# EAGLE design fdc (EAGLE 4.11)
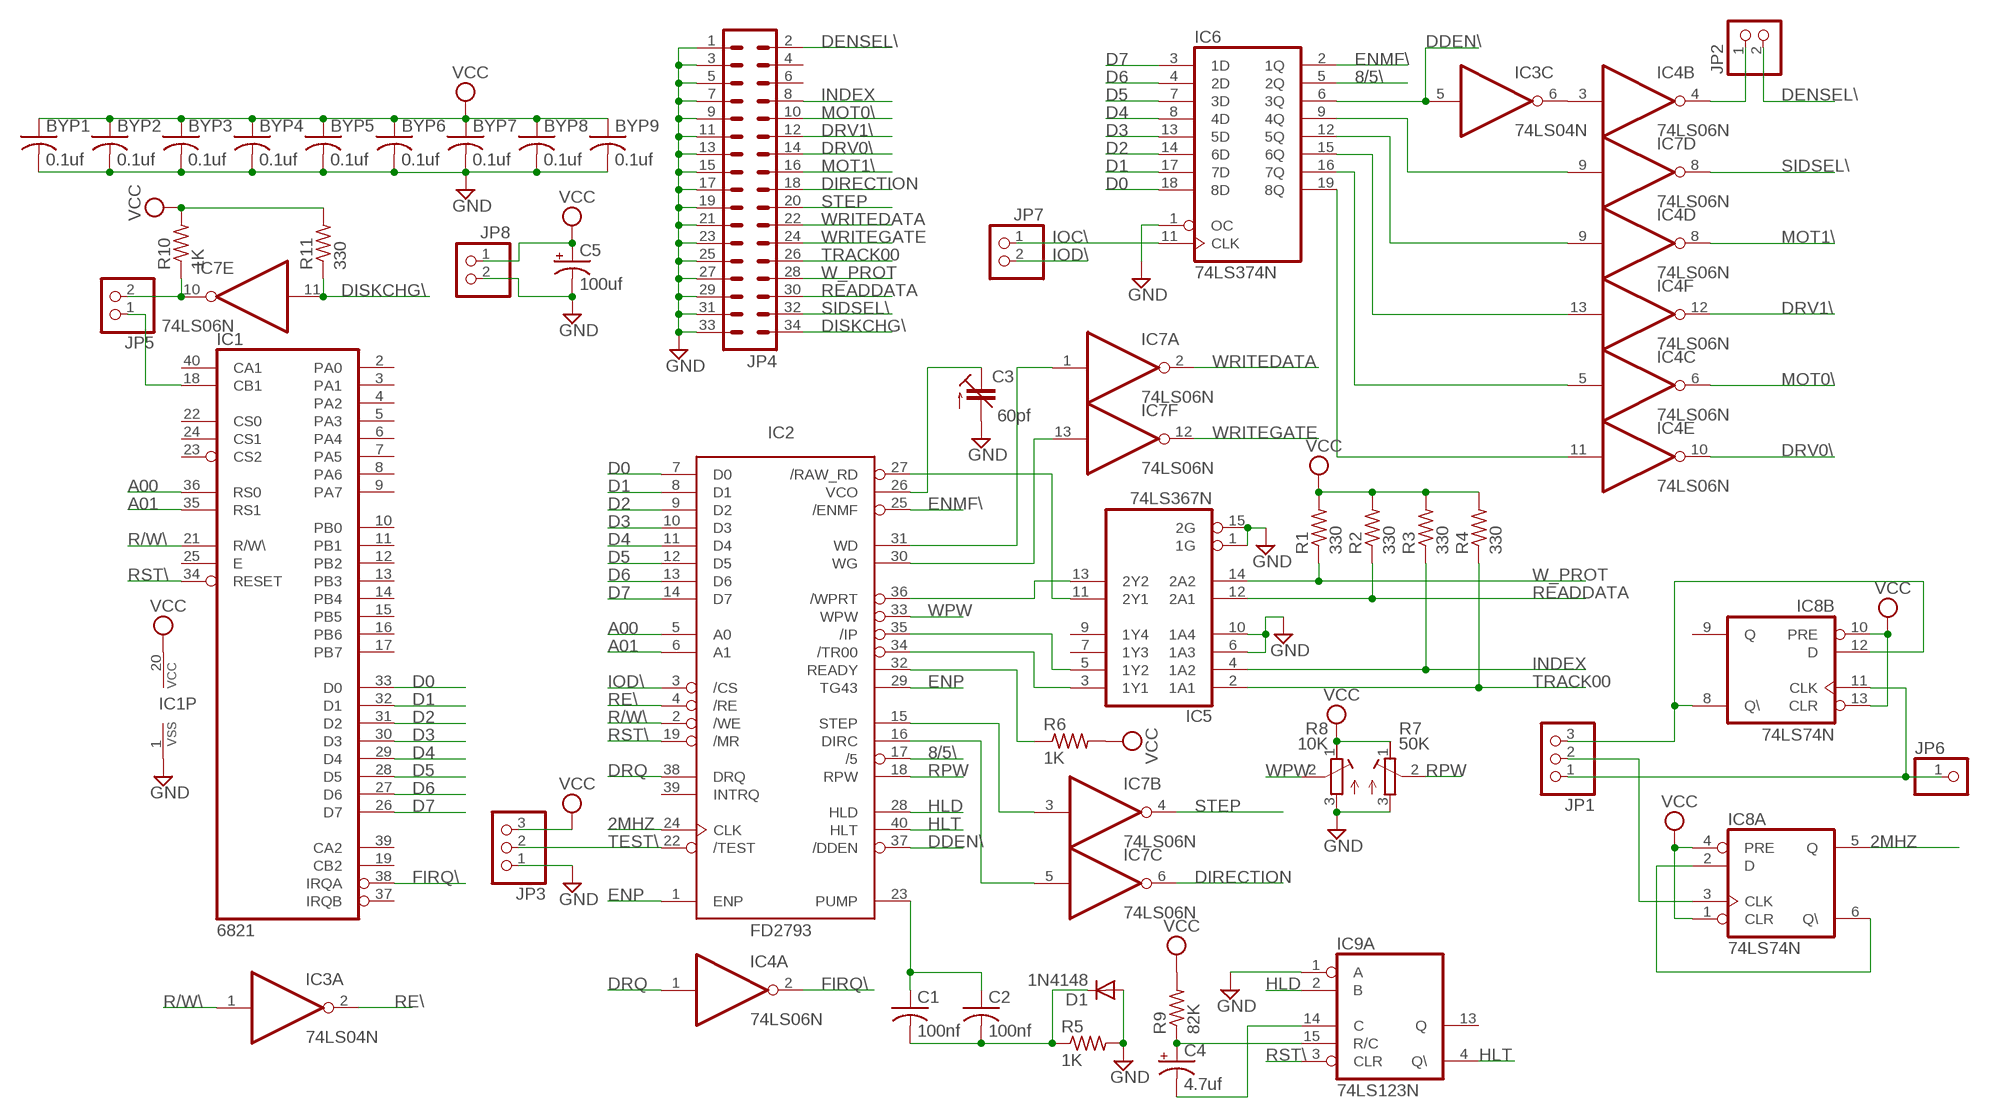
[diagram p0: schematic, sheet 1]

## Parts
BYP1  0.1uf  C-US050-025X075  [C050-025X075]
BYP2  0.1uf  C-US050-025X075  [C050-025X075]
BYP3  0.1uf  C-US050-025X075  [C050-025X075]
BYP4  0.1uf  C-US050-025X075  [C050-025X075]
BYP5  0.1uf  C-US050-025X075  [C050-025X075]
BYP6  0.1uf  C-US050-025X075  [C050-025X075]
BYP7  0.1uf  C-US050-025X075  [C050-025X075]
BYP8  0.1uf  C-US050-025X075  [C050-025X075]
BYP9  0.1uf  C-US050-025X075  [C050-025X075]
C1  100nf  C-US050-025X075  [C050-025X075]
C2  100nf  C-US050-025X075  [C050-025X075]
C3  60pf  C-TRIMM808  [CTRIM808-BC]
C4  4.7uf  CPOL-USE15-5AXIAL  [E15-5]
C5  100uf  CPOL-USE15-5AXIAL  [E15-5]
D1  1N4148  [DO35-10]
IC1  6821  [DIL40]
IC2  FD2793  [DIL40]
IC3  74LS04N  [DIL14]
IC4  74LS06N  [DIL14]
IC5  74LS367N  [DIL16]
IC6  74LS374N  [DIL20]
IC7  74LS06N  [DIL14]
IC8  74LS74N  [DIL14]
IC9  74LS123N  [DIL16]
JP1  PINHD-1X3  [1X03]
JP2  PINHD-1X2  [1X02]
JP3  PINHD-1X3  [1X03]
JP4  MA17-2  [MA17-2]
JP5  PINHD-1X2  [1X02]
JP6  PINHD-1X1  [1X01]
JP7  PINHD-1X2  [1X02]
JP8  PINHD-1X2  [1X02]
R1  330  R-US_0207/10  [0207/10]
R2  330  R-US_0207/10  [0207/10]
R3  330  R-US_0207/10  [0207/10]
R4  330  R-US_0207/10  [0207/10]
R5  1K  R-US_0207/10  [0207/10]
R6  1K  R-US_0207/10  [0207/10]
R7  50K  R-TRIMM43P  [RTRIM43P]
R8  10K  R-TRIMM43P  [RTRIM43P]
R9  82K  R-US_0207/10  [0207/10]
R10  1K  R-US_0207/10  [0207/10]
R11  330  R-US_0207/10  [0207/10]

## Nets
2MHZ: IC2.24(CLK) IC8.5(A:Q)
8/5\: IC2.17(/5) IC6.5(2Q)
A00: IC1.36(RS0) IC2.5(A0)
A01: IC1.35(RS1) IC2.6(A1)
CB1: IC1.18(CB1) JP5.1
D0: IC1.33(D0) IC2.7(D0) IC6.18(8D)
D1: IC1.32(D1) IC2.8(D1) IC6.17(7D)
D2: IC1.31(D2) IC2.9(D2) IC6.14(6D)
D3: IC1.30(D3) IC2.10(D3) IC6.13(5D)
D4: IC1.29(D4) IC2.11(D4) IC6.8(4D)
D5: IC1.28(D5) IC2.12(D5) IC6.7(3D)
D6: IC1.27(D6) IC2.13(D6) IC6.4(2D)
D7: IC1.26(D7) IC2.14(D7) IC6.3(1D)
DDEN\: IC2.37(/DDEN) IC3.5(C:I) IC6.6(3Q)
DENSEL\: JP2.2 JP4.2
DIRECTION: IC7.6(C:O) JP4.18
DISKCHG\: IC7.11(E:I) JP4.34 R11.1
DRQ: IC2.38(DRQ) IC4.1(A:I)
DRV0\: IC4.10(E:O) JP4.14
DRV1\: IC4.12(F:O) JP4.12
ENMF\: IC2.25(/ENMF) IC6.2(1Q)
ENP: IC2.1(ENP) IC2.29(TG43)
FIRQ\: IC1.38(IRQA) IC4.2(A:O)
GND: BYP1.2 BYP2.2 BYP3.2 BYP4.2 BYP5.2 BYP6.2 BYP7.2 BYP8.2 BYP9.2 C3.2(A) C5.- D1.A IC1.1(VSS) IC5.1(1G) IC5.6(1A3) IC5.10(1A4) IC5.15(2G) IC6.1(OC) IC9.1(A:A) JP3.1 JP4.1 JP4.3 JP4.5 JP4.7 JP4.9 JP4.11 JP4.13 JP4.15 JP4.17 JP4.19 JP4.21 JP4.23 JP4.25 JP4.27 JP4.29 JP4.31 JP4.33 JP8.2 R5.2 R7.3(E) R8.3(E)
HLD: IC2.28(HLD) IC9.2(A:B)
HLT: IC2.40(HLT) IC9.4(A:Q\)
INDEX: IC5.4(1A2) JP4.8 R3.1
IOC\: IC6.11(CLK) JP7.1
IOD\: IC2.3(/CS) JP7.2
MOT0\: IC4.6(C:O) JP4.10
MOT1\: IC4.8(D:O) JP4.16
N$1: IC3.6(C:O) IC4.3(B:I)
N$2: IC4.4(B:O) JP2.1
N$3: IC2.27(/RAW_RD) IC5.11(2Y1)
N$4: IC4.11(E:I) IC6.19(8Q)
N$5: IC4.5(C:I) IC6.16(7Q)
N$6: IC4.13(F:I) IC6.15(6Q)
N$7: IC4.9(D:I) IC6.12(5Q)
N$8: C4.+ IC9.15(A:R/C) R9.1
N$9: C4.- IC9.14(A:C)
N$10: IC2.32(READY) R6.1
N$11: IC6.9(4Q) IC7.9(D:I)
N$12: IC2.16(DIRC) IC7.5(C:I)
N$13: IC7.10(E:O) JP5.2 R10.1
N$14: IC2.34(/TR00) IC5.3(1Y1)
N$15: IC2.35(/IP) IC5.5(1Y2)
N$16: IC8.8(B:Q\) IC8.12(B:D) JP1.3
N$17: IC2.36(/WPRT) IC5.13(2Y2)
N$18: IC8.11(B:CLK) JP1.1 JP6.1
N$19: C3.1(E) IC2.26(VCO)
N$20: C1.2 C2.2 D1.C R5.1
N$21: IC2.31(WD) IC7.1(A:I)
N$22: IC2.30(WG) IC7.13(F:I)
N$24: IC2.15(STEP) IC7.3(B:I)
N$25: IC8.3(A:CLK) JP1.2
N$26: IC8.2(A:D) IC8.6(A:Q\)
PUMP: C1.1 C2.1 IC2.23(PUMP)
R/W\: IC1.21(R/W\) IC2.2(/WE) IC3.1(A:I)
RE\: IC2.4(/RE) IC3.2(A:O)
READDATA: IC5.12(2A1) JP4.30 R2.1
RPW: IC2.18(RPW) R7.2(S)
RST\: IC1.34(RESET) IC2.19(/MR) IC9.3(A:CLR)
SIDSEL\: IC7.8(D:O) JP4.32
STEP: IC7.4(B:O) JP4.20
TEST\: IC2.22(/TEST) JP3.2
TRACK00: IC5.2(1A1) JP4.26 R4.1
VCC [Power]: BYP1.1 BYP2.1 BYP3.1 BYP4.1 BYP5.1 BYP6.1 BYP7.1 BYP8.1 BYP9.1 C5.+ IC1.20(VCC) IC8.1(A:CLR) IC8.4(A:PRE) IC8.10(B:PRE) IC8.13(B:CLR) JP3.3 JP8.1 R1.2 R2.2 R3.2 R4.2 R6.2 R7.1(A) R8.1(A) R9.2 R10.2 R11.2
W_PROT: IC5.14(2A2) JP4.28 R1.1
WPW: IC2.33(WPW) R8.2(S)
WRITEDATA: IC7.2(A:O) JP4.22
WRITEGATE: IC7.12(F:O) JP4.24
Unconnected: IC1.2(PA0) IC1.3(PA1) IC1.4(PA2) IC1.5(PA3) IC1.6(PA4) IC1.7(PA5) IC1.8(PA6) IC1.9(PA7) IC1.10(PB0) IC1.11(PB1) IC1.12(PB2) IC1.13(PB3) IC1.14(PB4) IC1.15(PB5) IC1.16(PB6) IC1.17(PB7) IC1.19(CB2) IC1.22(CS0) IC1.23(CS2) IC1.24(CS1) IC1.25(E) IC1.37(IRQB) IC1.39(CA2) IC1.40(CA1) IC2.39(INTRQ) IC3.3(B:I) IC3.4(B:O) IC3.8(D:O) IC3.9(D:I) IC3.10(E:O) IC3.11(E:I) IC3.12(F:O) IC3.13(F:I) IC5.7(1Y3) IC5.9(1Y4) IC8.9(B:Q) IC9.5(B:Q) IC9.6(B:C) IC9.7(B:R/C) IC9.9(B:A) IC9.10(B:B) IC9.11(B:CLR) IC9.12(B:Q\) IC9.13(A:Q) JP4.4 JP4.6

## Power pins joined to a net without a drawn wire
GND: IC2.20(GND) IC3.7(P:GND) IC4.7(P:GND) IC5.8(GND) IC6.10(GND) IC7.7(P:GND) IC8.7(P:GND) IC9.8(P:GND)
VCC: IC2.21(VCC) IC3.14(P:VCC) IC4.14(P:VCC) IC5.16(VCC) IC6.20(VCC) IC7.14(P:VCC) IC8.14(P:VCC) IC9.16(P:VCC)

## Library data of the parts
BYP1-BYP9 C1 C2 = rcl:C-US: CAPACITOR, American symbol
C3 = rcl:C-TRIMM: Trimm capacitor
C4 C5 = rcl:CPOL-US: POLARIZED CAPACITOR, American symbol
D1 = diode:1N4148: DIODE
IC1 = micro-motorola:6821: MICROCONTROLLER/MEMORY DEVICE
IC2 = western-digital-devices:FD2793: FD2793 Floppy Disk Formatter/Controller
IC3 = 74xx-jameco:74*04: Hex INVERTER
IC4 IC7 = 74xx-jameco:74*06: Hex INVERTER, open collector high-voltage output
IC5 = 74xx-jameco:74*367: Hex BUS DRIVER, 3-state
IC6 = 74xx-jameco:74*374: Octal D type transparent LATCH, edge triggered
IC8 = 74xx-jameco:74*74: Dual D type positive edge triggered FLIP FLOP, preset and clear
IC9 = 74xx-jameco:74*123: Retriggerable monostable MULTIVIBRATOR
JP1 JP3 = pinhead:PINHD-1X3: PIN HEADER
JP2 JP5 JP7 JP8 = pinhead:PINHD-1X2: PIN HEADER
JP4 = con-lstb:MA17-2: PIN HEADER
JP6 = pinhead:PINHD-1X1: PIN HEADER
R1-R6 R9-R11 = rcl:R-US_: RESISTOR, American symbol
R7 R8 = rcl:R-TRIMM: Trimm resistor

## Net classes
1 Power: width 0.508 mm, drill 0.254 mm, clearance 0.254 mm

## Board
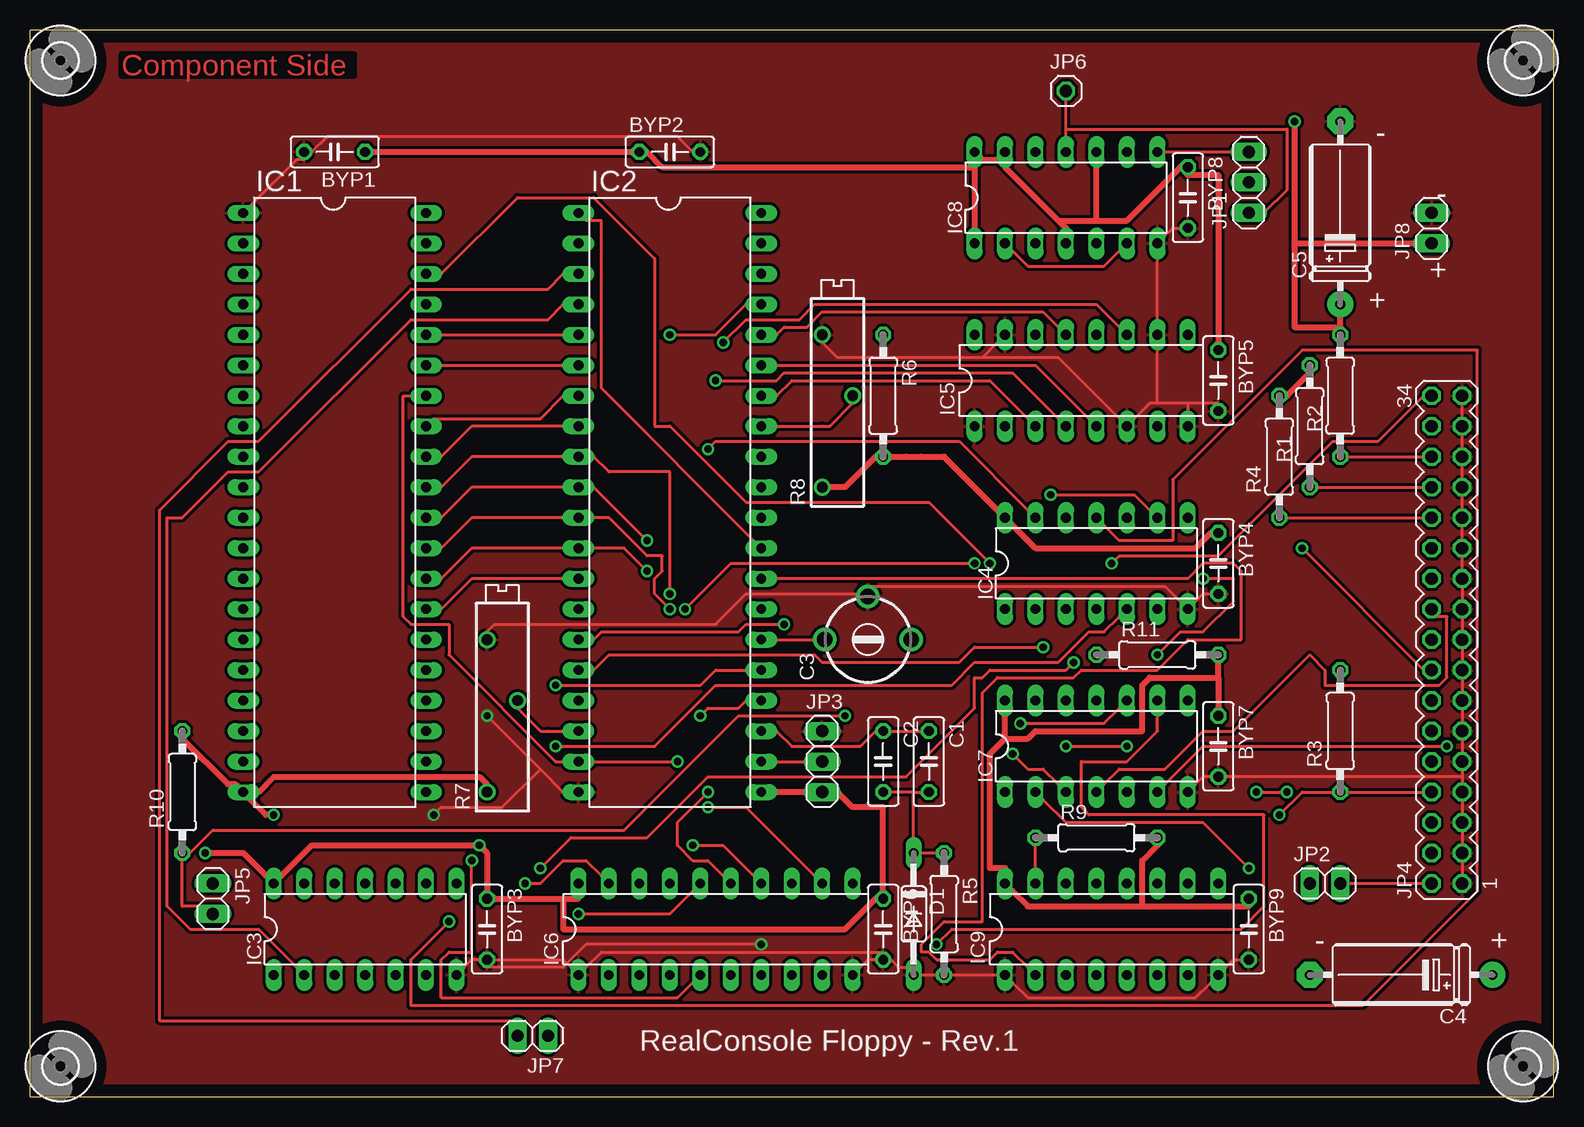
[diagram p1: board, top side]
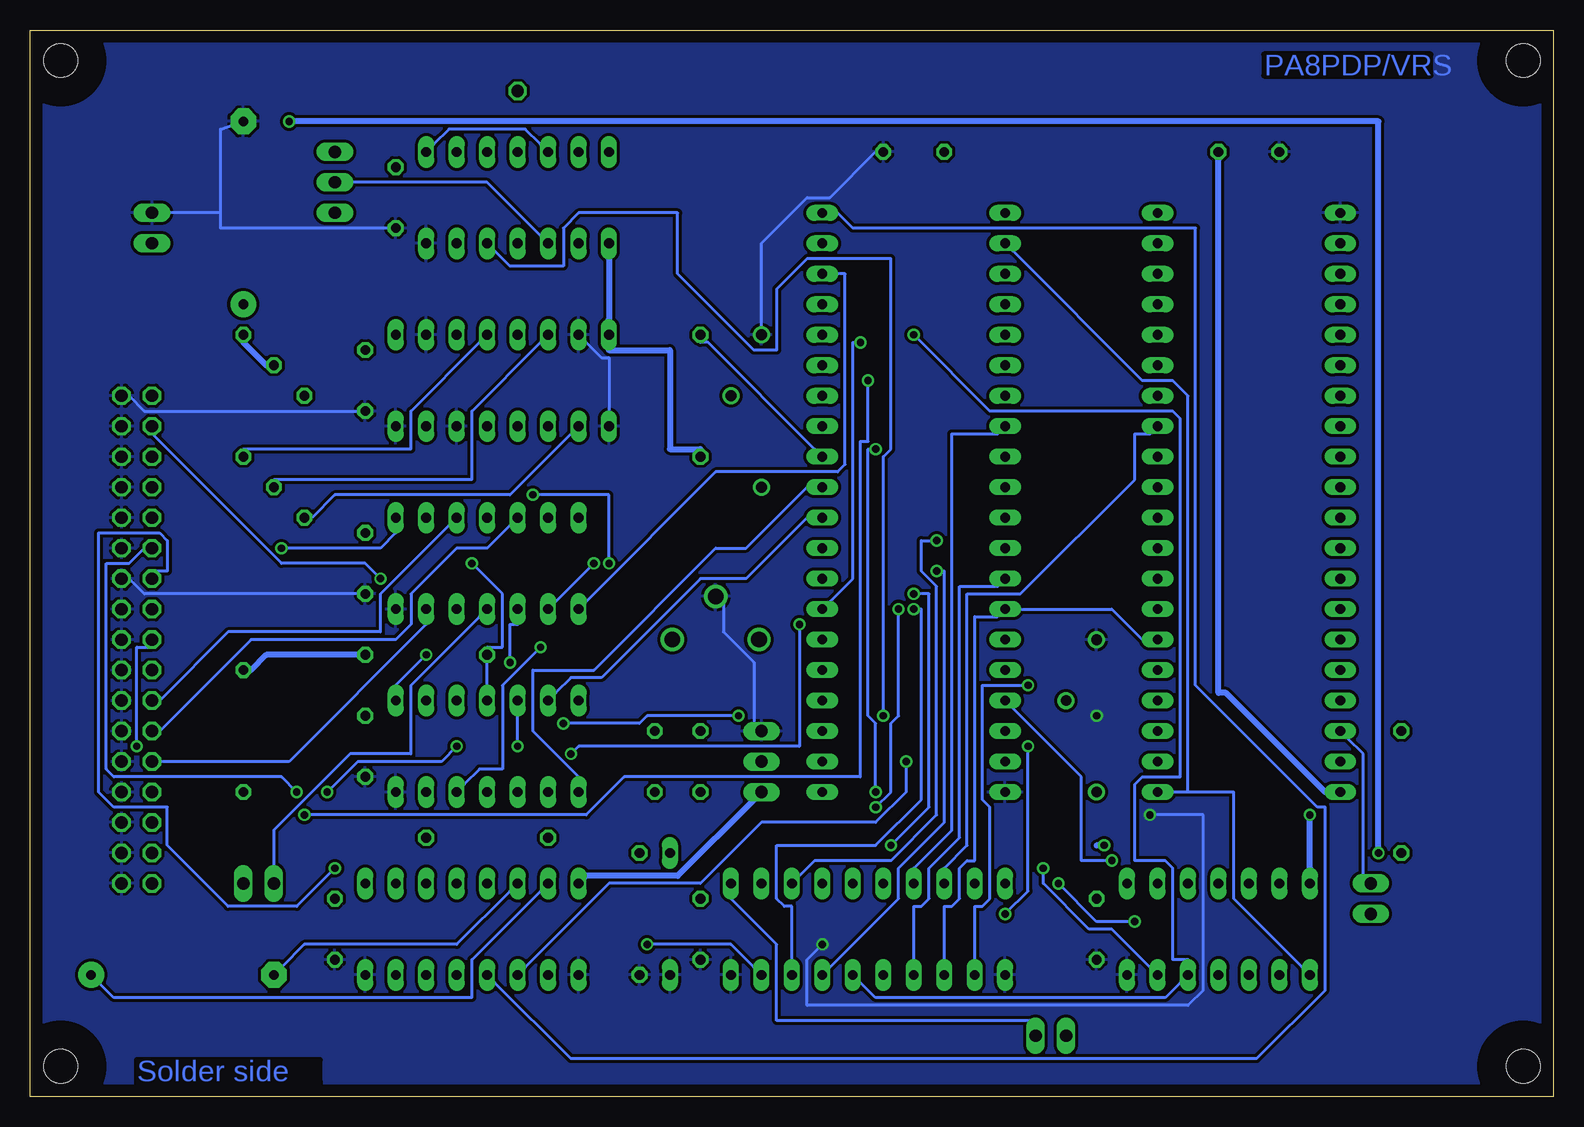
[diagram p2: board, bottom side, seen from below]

Size 127.01 x 88.9 mm. Coordinates in mm from the lower left corner, seen from the top.
Outline: 0,0 127.01,0.01
Outline: 0,0 0,88.9 127,88.9 127,0
Copper layers (1*16): Top 0.035mm / dielectric 1.5mm / Bottom 0.035mm
Design rules "olimex10mil": minimum track width 10mil, minimum drill 24mil, track to track 10mil, track to pad 10mil, pad to pad 10mil, via to via 10mil, smd to smd 10mil, copper to edge 40mil, drill to drill 10mil, minimum pad ring 10mil, minimum via ring 8mil, stop-mask expansion 0mil, vias tented up to drill 0mil, thermal gap 10mil

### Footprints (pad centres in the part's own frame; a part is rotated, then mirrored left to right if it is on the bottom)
C050-025X075 = drill 0.813 octagon: 1 -2.54,0; 2 2.54,0
CTRIM808-BC = drill 1.3 round: 1 -3.607,0; 2 0,3.607; 3 3.607,0
E15-5 = drill 0.813 pad 2.159 round: + -7.62,0 | drill 0.813 pad 2.159 octagon: - 7.62,0
DO35-10 = drill 0.813 long: A 5.08,0; C -5.08,0
DIL40 = drill 0.813 long: 1 -24.13,-7.62; 2 -21.59,-7.62; 3 -19.05,-7.62; 4 -16.51,-7.62; 5 -13.97,-7.62; 6 -11.43,-7.62; 7 -8.89,-7.62; 8 -6.35,-7.62; 9 -3.81,-7.62; 10 -1.27,-7.62; 11 1.27,-7.62; 12 3.81,-7.62; 13 6.35,-7.62; 14 8.89,-7.62; 15 11.43,-7.62; 16 13.97,-7.62; 17 16.51,-7.62; 18 19.05,-7.62; 19 21.59,-7.62; 20 24.13,-7.62; 21 24.13,7.62; 22 21.59,7.62; 23 19.05,7.62; 24 16.51,7.62; 25 13.97,7.62; 26 11.43,7.62; 27 8.89,7.62; 28 6.35,7.62; 29 3.81,7.62; 30 1.27,7.62; 31 -1.27,7.62; 32 -3.81,7.62; 33 -6.35,7.62; 34 -8.89,7.62; 35 -11.43,7.62; 36 -13.97,7.62; 37 -16.51,7.62; 38 -19.05,7.62; 39 -21.59,7.62; 40 -24.13,7.62
DIL14 = drill 0.813 long: 1 -7.62,-3.81; 2 -5.08,-3.81; 3 -2.54,-3.81; 4 0,-3.81; 5 2.54,-3.81; 6 5.08,-3.81; 7 7.62,-3.81; 8 7.62,3.81; 9 5.08,3.81; 10 2.54,3.81; 11 0,3.81; 12 -2.54,3.81; 13 -5.08,3.81; 14 -7.62,3.81
DIL16 = drill 0.813 long: 1 -8.89,-3.81; 2 -6.35,-3.81; 3 -3.81,-3.81; 4 -1.27,-3.81; 5 1.27,-3.81; 6 3.81,-3.81; 7 6.35,-3.81; 8 8.89,-3.81; 9 8.89,3.81; 10 6.35,3.81; 11 3.81,3.81; 12 1.27,3.81; 13 -1.27,3.81; 14 -3.81,3.81; 15 -6.35,3.81; 16 -8.89,3.81
DIL20 = drill 0.813 long: 1 -11.43,-3.81; 2 -8.89,-3.81; 3 -6.35,-3.81; 4 -3.81,-3.81; 5 -1.27,-3.81; 6 1.27,-3.81; 7 3.81,-3.81; 8 6.35,-3.81; 9 8.89,-3.81; 10 11.43,-3.81; 11 11.43,3.81; 12 8.89,3.81; 13 6.35,3.81; 14 3.81,3.81; 15 1.27,3.81; 16 -1.27,3.81; 17 -3.81,3.81; 18 -6.35,3.81; 19 -8.89,3.81; 20 -11.43,3.81
1X03 = drill 1.016 long: 1 -2.54,0; 2 0,0; 3 2.54,0
1X02 = drill 1.016 long: 1 -1.27,0; 2 1.27,0
MA17-2 = drill 1.016 octagon: 1 -20.32,-1.27; 2 -20.32,1.27; 3 -17.78,-1.27; 4 -17.78,1.27; 5 -15.24,-1.27; 6 -15.24,1.27; 7 -12.7,-1.27; 8 -12.7,1.27; 9 -10.16,-1.27; 10 -10.16,1.27; 11 -7.62,-1.27; 12 -7.62,1.27; 13 -5.08,-1.27; 14 -5.08,1.27; 15 -2.54,-1.27; 16 -2.54,1.27; 17 0,-1.27; 18 0,1.27; 19 2.54,-1.27; 20 2.54,1.27; 21 5.08,-1.27; 22 5.08,1.27; 23 7.62,-1.27; 24 7.62,1.27; 25 10.16,-1.27; 26 10.16,1.27; 27 12.7,-1.27; 28 12.7,1.27; 29 15.24,-1.27; 30 15.24,1.27; 31 17.78,-1.27; 32 17.78,1.27; 33 20.32,-1.27; 34 20.32,1.27
1X01 = drill 1.016 octagon: 1 0,0
0207/10 = drill 0.813 octagon: 1 -5.08,0; 2 5.08,0
RTRIM43P = drill 0.9 round: 1 -7.62,1.27; 2 0,-1.27; 3 5.08,1.27
2,8 = hole 2.8: 0,0

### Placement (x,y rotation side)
BYP1  25.4,78.74 180 top
BYP2  53.34,78.74 0 top
BYP3  38.1,13.97 270 top
BYP4  99.06,44.45 270 top
BYP5  99.06,59.69 270 top
BYP6  71.12,13.97 270 top
BYP7  99.06,29.21 270 top
BYP8  96.52,74.93 270 top
BYP9  101.6,13.97 270 top
C1  74.93,27.94 270 top
C2  71.12,27.94 270 top
C3  69.85,38.1 0 top
C4  114.3,10.16 180 top
C5  109.22,73.66 90 top
D1  73.66,15.24 270 top
IC1  25.4,49.53 270 top
IC2  53.34,49.53 270 top
IC3  27.94,13.97 0 top
IC4  88.9,44.45 0 top
IC5  87.63,59.69 0 top
IC6  57.15,13.97 0 top
IC7  88.9,29.21 0 top
IC8  86.36,74.93 0 top
IC9  90.17,13.97 0 top
JP1  101.6,76.2 90 top
JP2  107.95,17.78 0 top
JP3  66.04,27.94 270 top
JP4  118.11,38.1 90 top
JP5  15.24,16.51 270 top
JP6  86.36,83.82 0 top
JP7  41.91,5.08 180 top
JP8  116.84,72.39 90 top
R1  106.68,55.88 90 top
R2  109.22,58.42 90 top
R3  109.22,30.48 90 top
R4  104.14,53.34 90 top
R5  76.2,15.24 270 top
R6  71.12,58.42 270 top
R7  39.37,33.02 90 top
R8  67.31,58.42 90 top
R9  88.9,21.59 0 top
R10  12.7,25.4 90 top
R11  93.98,36.83 0 top
U$3  [2,8]  2.54,86.36 0 top
U$4  [2,8]  2.54,2.54 0 top
U$5  [2,8]  124.46,86.36 0 top
U$6  [2,8]  124.46,2.54 0 top

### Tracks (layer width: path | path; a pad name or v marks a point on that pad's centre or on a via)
2MHZ  (via drill 0.61)
  Top 0.254: v55.88,31.75 56.52,32.38 59.05,32.38 59.69,33.02 IC2.24
  Bottom 0.254: v55.88,31.75 55.88,53.34 55.24,53.98 55.24,69.85 62.23,69.85 64.77,67.31 64.77,62.23 66.67,62.23 73.03,68.58 73.03,73.66 81.28,73.66 82.55,72.39 82.55,69.22 87,69.22 88.27,70.48 IC8.5
8/5\  (via drill 0.61)
  Top 0.254: v36.83,19.68 36.83,12.06 34.92,12.06 34.29,11.43 34.29,8.26 53.98,8.26 55.24,9.53 IC6.5
  Bottom 0.254: v36.83,19.68 39.37,19.68 39.37,26.67 45.09,32.38 IC2.17
A00
  Top 0.254: IC1.36 34.29,63.5 44.45,63.5 IC2.5
A01
  Top 0.254: IC1.35 34.29,60.96 44.45,60.96 IC2.6
CB1
  Bottom 0.254: IC1.18 17.14,29.84 15.88,28.57 15.88,18.41 JP5.1
D0
  Top 0.254: IC2.7 44.45,58.42 42.55,56.52 33.66,56.52 IC1.33
  Bottom 0.254: IC6.18 50.8,19.05 48.9,20.95 48.9,41.91 44.45,41.91 34.92,51.44 34.92,55.24 33.66,55.24 IC1.33
D1
  Top 0.254: IC1.32 34.29,53.34 36.83,55.88 44.45,55.88 IC2.8
  Bottom 0.254: IC6.17 53.34,19.05 50.16,22.23 50.16,55.24 46.35,55.24 IC2.8
D2  (via drill 0.61)
  Top 0.254: v55.24,20.95 57.78,20.95 60.33,18.41 IC6.14 | v53.34,41.91 53.34,52.07 48.26,52.07 46.99,53.34 IC2.9 44.45,53.34 36.83,53.34 34.29,50.8 IC1.31
  Bottom 0.254: v55.24,20.95 52.07,24.13 52.07,41.91 v53.34,41.91
D3  (via drill 0.61)
  Top 0.254: v51.44,46.35 46.99,50.8 IC2.10 44.45,50.8 36.83,50.8 34.29,48.26 IC1.30
  Bottom 0.254: v51.44,46.35 52.7,46.35 52.7,43.81 51.44,42.55 51.44,23.5 55.24,19.68 61.59,19.68 62.87,18.41 IC6.13
D4  (via drill 0.61)
  Top 0.254: v53.34,40.64 52.07,41.91 52.07,43.18 52.7,43.81 52.7,45.09 51.44,45.09 48.26,48.26 46.99,48.26 IC2.11 44.45,48.26 36.83,48.26 34.29,45.72 IC1.29
  Bottom 0.254: v53.34,40.64 52.7,40.64 52.7,24.77 56.52,20.95 64.77,20.95 64.77,16.51 64.14,15.88 63.5,15.88 63.5,11.43 IC6.8
D5  (via drill 0.61)
  Top 0.254: v51.44,43.81 49.53,45.72 46.99,45.72 IC2.12 44.45,45.72 36.83,45.72 34.29,43.18 IC1.28
  Bottom 0.254: v51.44,43.81 50.8,43.81 50.8,22.86 54.61,19.05 54.61,16.51 60.33,10.79 IC6.7
D6
  Top 0.254: IC1.27 34.29,40.64 36.83,43.18 44.45,43.18 IC2.13
  Bottom 0.254: IC6.4 53.34,11.43 53.34,15.88 52.7,15.88 52.07,16.51 52.07,19.05 49.53,21.59 49.53,42.55 46.35,42.55 IC2.13
D7
  Bottom 0.254: IC6.3 50.8,11.43 50.8,15.88 50.16,15.88 49.53,16.51 49.53,19.05 48.9,19.68 48.26,19.68 48.26,40.01 46.35,40.01 IC2.14 44.45,40.64 36.83,40.64 34.29,38.1 IC1.26
DDEN\  (via drill 0.61)
  Top 0.254: v53.34,63.5 57.15,63.5 59.69,66.04 IC2.37
  Bottom 0.254: IC6.6 57.78,9.53 56.52,8.26 32.38,8.26 31.11,9.53 IC3.5 30.48,11.43 31.75,11.43 31.75,19.05 32.38,19.68 34.92,19.68 34.92,26.04 34.29,26.67 31.11,26.67 31.11,56.52 31.75,57.15 46.99,57.15 v53.34,63.5
DENSEL\
  Top 0.254: JP2.2 109.86,17.78 116.2,17.78 JP4.2
DIRECTION  (via drill 0.61)
  Top 0.254: v118.11,29.21 97.79,29.21 94.61,26.04 IC7.6
  Bottom 0.254: v118.11,29.21 118.11,37.47 116.84,37.47 JP4.18
DISKCHG\  (via drill 0.61)
  Top 0.254: v90.17,44.45 90.81,45.09 99.06,45.09 108.58,54.61 112.39,54.61 116.2,58.42 JP4.34
  Bottom 0.254: IC7.11 88.9,34.29 88.9,36.2 R11.1 88.9,37.47 87.63,37.47 87.63,41.91 v90.17,44.45
DRQ
  Bottom 0.254: IC4.1 80.64,41.27 69.85,52.07 59.69,52.07 59.05,52.7 59.05,68.58 59.69,68.58 IC2.38
DRV0\
  Bottom 0.254: IC4.10 92.08,47.62 97.79,41.91 97.79,38.73 110.49,38.73 116.2,33.02 JP4.14
DRV1\
  Bottom 0.254: IC4.12 87,47.62 88.9,45.72 91.44,45.72 95.25,41.91 95.25,39.37 96.52,38.1 108.58,38.1 116.2,30.48 JP4.12
ENMF\  (via drill 0.61)
  Top 0.254: v43.81,34.29 55.88,34.29 57.15,35.56 59.69,35.56 IC2.25
  Bottom 0.254: v43.81,34.29 47.62,34.29 47.62,24.77 46.99,24.13 46.99,16.51 47.62,15.88 48.26,15.88 48.26,11.43 IC6.2
ENP
  Top 0.254: IC2.29 60.33,46.35 47.62,59.05 47.62,73.03 46.35,73.03 IC2.1
FIRQ\  (via drill 0.61)
  Top 0.254: v80.01,44.45 74.93,49.53 59.69,49.53 53.34,55.88 52.07,55.88 52.07,69.85 46.99,74.93 40.64,74.93 34.29,68.58 IC1.38
  Bottom 0.254: v80.01,44.45 83.19,41.27 IC4.2
GND  (via drill 0.61)
  Top 0.254: BYP8.2 95.89,72.39 95.25,72.39 94.61,71.75 IC8.7 93.98,69.85 93.98,64.77 IC5.10 93.98,62.23 93.98,57.78 | 96.52,57.78 99.06,57.78 BYP5.2 | 96.52,57.78 93.98,57.78 | 93.98,57.78 93.34,57.78 92.08,56.52 IC5.6 90.81,56.52 85.72,61.59 79.38,61.59 | 96.52,57.78 96.52,57.15 IC5.8 | IC1.1 18.41,74.3 22.23,78.11 22.86,78.11 BYP1.2 23.5,78.74 24.77,80.01 53.98,80.01 55.24,78.74 BYP2.2 | 79.38,61.59 67.94,61.59 67.31,61.59 66.04,62.87 R8.3 | 79.38,61.59 80.64,62.87 IC5.15 | BYP4.2 98.42,41.91 97.79,41.91 97.16,41.27 IC4.7 95.89,41.27 94.61,42.55 69.85,42.55 C3.2 69.22,41.91 59.69,41.91 57.15,39.37 39.37,39.37 38.73,39.37 38.1,38.73 R7.3 | 42.55,27.3 v38.1,31.75 | 42.55,27.3 44.45,25.4 IC2.20 | IC7.7 97.16,26.04 97.79,26.67 98.42,26.67 BYP7.2 99.69,26.67 119.38,26.67 | JP4.1 119.38,18.41 119.38,19.68 JP4.3 119.38,20.95 119.38,22.23 JP4.5 119.38,23.5 119.38,24.77 JP4.7 119.38,26.04 119.38,26.67 | 119.38,26.67 119.38,27.3 JP4.9 119.38,28.57 119.38,29.84 JP4.11 119.38,31.11 119.38,32.38 JP4.13 119.38,33.66 119.38,34.92 JP4.15 119.38,36.2 119.38,37.47 JP4.17 119.38,38.73 119.38,40.01 JP4.19 119.38,41.27 119.38,42.55 JP4.21 119.38,43.81 119.38,45.09 JP4.23 119.38,46.35 119.38,47.62 JP4.25 119.38,48.9 119.38,50.16 JP4.27 119.38,51.44 119.38,52.7 JP4.29 119.38,53.98 119.38,55.24 JP4.31 119.38,56.52 119.38,57.78 JP4.33 | IC3.7 36.2,10.79 36.83,11.43 37.47,11.43 BYP3.2 | BYP3.2 38.73,11.43 44.45,11.43 45.09,10.79 IC6.1 46.35,10.79 47.62,12.06 71.12,12.06 BYP6.2 | BYP9.2 100.97,11.43 100.33,11.43 99.69,10.79 IC9.8 98.42,9.53 97.16,8.26 83.19,8.26 81.92,9.53 IC9.1 80.64,10.16 76.83,10.16 R5.2 75.56,10.16 74.3,10.16 D1.A 73.03,10.79 72.39,10.79 71.75,11.43 BYP6.2
  Top 0.254: IC6.10 69.22,10.79 69.85,11.43 70.48,11.43 BYP6.2 | v60.96,12.7 46.35,12.7 44.45,10.79 38.1,10.79 BYP3.2 | v33.66,23.5 34.29,24.13 39.37,24.13 42.55,27.3
  Bottom 0.254: BYP2.2 56.52,78.74 60.33,74.93 62.23,74.93 66.04,71.12 66.04,64.14 R8.3 | IC5.1 78.74,57.15 78.74,61.59 79.38,61.59 80.64,62.87 IC5.15 | JP3.1 66.67,31.11 66.67,36.2 69.22,38.73 69.22,41.27 C3.2 | BYP4.2 99.69,41.91 117.47,41.91 118.75,43.18 JP4.21 | BYP5.2 99.69,57.15 117.47,57.15 118.75,58.42 JP4.33 | v60.96,12.7 62.23,11.43 62.23,7.62 30.48,7.62 29.21,8.89 29.21,23.5 v33.66,23.5 | 111.12,73.66 111.12,72.39 97.16,72.39 BYP8.2 | 111.12,73.66 111.12,80.64 C5.- | 111.12,73.66 115.57,73.66 JP8.2
  pour Bottom (isolate 0.254): 0,0 0,88.9 127,88.9 127,0
  pour Top (isolate 0.254): 0,0 0,88.9 127,88.9 127,0
HLD
  Top 0.254: IC2.28 62.23,43.18 96.52,43.18 97.79,44.45 100.33,44.45 100.97,43.81 100.97,38.1 96.52,38.1 93.98,35.56 87.63,35.56 87,34.92 80.64,34.92 79.38,33.66 79.38,14.61 76.2,14.61 74.3,12.7 74.3,12.06 74.93,12.06 75.56,11.43 80.01,11.43 80.64,12.06 81.92,12.06 83.19,10.79 IC9.2
HLT
  Bottom 0.254: IC9.4 88.27,9.53 81.92,3.17 24.77,3.17 19.05,8.89 19.05,24.13 19.68,24.13 29.84,34.29 29.84,72.39 58.42,72.39 59.69,73.66 IC2.40
INDEX  (via drill 0.61)
  Top 0.254: v57.15,59.69 62.23,59.69 62.87,60.33 81.92,60.33 85.72,56.52 IC5.4 | v104.14,23.5 106.05,25.4 108.58,25.4 R3.1 109.86,25.4 116.2,25.4 JP4.8
  Bottom 0.254: v57.15,59.69 57.15,54.61 57.78,54.61 57.78,26.67 77.47,26.67 80.64,23.5 v104.14,23.5
IOC\
  Bottom 0.254: IC6.11 68.58,16.51 64.77,12.7 64.77,6.35 43.18,6.35 JP7.1
IOD\
  Top 0.254: IC2.3 44.45,68.58 43.18,67.31 31.75,67.31 19.05,54.61 16.51,54.61 10.79,48.9 10.79,6.35 40.64,6.35 JP7.2
MOT0\
  Bottom 0.254: IC4.6 93.98,39.37 105.41,27.94 116.2,27.94 JP4.10
MOT1\  (via drill 0.61)
  Top 0.254: v106.05,45.72 116.2,35.56 JP4.16
  Bottom 0.254: v106.05,45.72 97.79,45.72 96.52,46.99 IC4.8
N$1  (via drill 0.61)
  Top 0.254: v42.55,19.05 45.09,21.59 51.44,21.59 56.52,26.67 73.03,26.67 78.74,32.38 78.74,34.92 79.38,34.92 80.01,35.56 86.36,35.56 v87,36.2
  Bottom 0.254: v42.55,19.05 42.55,17.78 38.73,13.97 36.83,13.97 33.66,10.79 IC3.6 | v87,36.2 87,39.37 86.36,39.37 IC4.3
N$2
  Bottom 0.254: IC4.4 89.53,40.01 95.25,34.29 95.25,28.57 100.33,28.57 106.68,22.23 106.68,19.05 JP2.1
N$3  (via drill 0.61)
  Top 0.254: v57.78,62.87 59.69,64.77 64.14,64.77 65.41,66.04 88.9,66.04 90.81,64.14 IC5.11
  Bottom 0.254: v57.78,62.87 58.42,62.87 58.42,43.18 60.33,41.27 IC2.27
N$4  (via drill 0.61)
  Top 0.254: v41.27,17.78 42.55,17.78 44.45,19.68 46.35,19.68 47.62,18.41 IC6.19 | v34.92,14.61 31.75,11.43 31.75,7.62 111.12,7.62 120.65,17.14 120.65,62.23 106.05,62.23 95.25,51.44 95.25,46.35 90.81,46.35 89.53,47.62 IC4.11
  Bottom 0.254: v41.27,17.78 38.1,14.61 v34.92,14.61
N$5  (via drill 0.61)
  Top 0.254: v45.72,15.24 53.34,15.24 55.24,17.14 IC6.16 | v43.81,29.21 52.07,29.21 57.15,34.29 76.83,34.29 78.74,36.2 85.72,36.2 88.27,38.73 89.53,38.73 90.81,40.01 IC4.5
  Bottom 0.254: v45.72,15.24 43.81,17.14 v43.81,29.21
N$6  (via drill 0.61)
  Top 0.254: v56.52,25.4 53.98,22.86 53.98,20.95 55.24,19.68 56.52,19.68 57.78,18.41 IC6.15 | v56.52,53.98 57.15,54.61 77.47,54.61 83.19,48.9 IC4.13
  Bottom 0.254: v56.52,25.4 56.52,31.11 57.15,31.75 57.15,53.98 v56.52,53.98
N$7  (via drill 0.61)
  Top 0.254: v56.52,24.13 59.69,24.13 65.41,18.41 IC6.12 | v54.61,40.64 58.42,44.45 v78.74,44.45 | v85.09,50.16 92.08,50.16 93.34,48.9 IC4.9
  Bottom 0.254: v56.52,24.13 55.24,25.4 55.24,31.11 54.61,31.75 v54.61,40.64 | v78.74,44.45 78.74,50.16 v85.09,50.16
N$8
  Top 0.254: R9.1 83.82,20.95 83.82,19.05 IC9.15
  Bottom 0.254: IC9.15 84.45,17.14 90.17,11.43 90.17,8.26 120.02,8.26 121.28,9.53 C4.+
N$9
  Bottom 0.254: IC9.14 87,17.14 91.44,12.7 104.14,12.7 106.05,10.79 C4.-
N$10
  Bottom 0.254: IC2.32 61.59,53.98 70.48,62.87 71.12,62.87 R6.1
N$11  (via drill 0.61)
  Top 0.254: v75.56,12.7 76.83,13.97 100.97,13.97 102.87,15.88 102.87,23.5 88.27,23.5 87.63,24.13 87.63,27.94 91.44,27.94 93.98,30.48 93.98,31.75 IC7.9
  Bottom 0.254: v75.56,12.7 68.58,12.7 66.67,10.79 IC6.9
N$12  (via drill 0.61)
  Top 0.254: v84.45,37.47 78.74,37.47 77.47,36.2 66.04,36.2 65.41,36.83 48.26,36.83 46.99,35.56 IC2.16
  Bottom 0.254: v84.45,37.47 87.63,34.29 87.63,27.3 89.53,27.3 90.81,26.04 IC7.5
N$13  (via drill 0.61)
  Top 0.254: JP5.2 14.61,15.88 12.7,15.88 12.7,19.68 R10.1 13.34,20.32 15.24,22.23 49.53,22.23 59.05,31.75 v67.94,31.75 | v82.55,31.11 89.53,31.11 90.81,32.38 IC7.10
  Bottom 0.254: v82.55,31.11 76.2,31.11 75.56,31.75 v67.94,31.75
N$14
  Top 0.254: IC2.34 62.23,58.42 63.5,59.69 80.01,59.69 83.19,56.52 IC5.3
N$15
  Top 0.254: IC2.35 62.23,60.96 83.82,60.96 88.27,56.52 IC5.5
N$16
  Top 0.254: JP1.3 100.33,78.74 94.61,78.74 IC8.8
  Bottom 0.254: IC8.12 84.45,79.38 85.72,80.64 92.08,80.64 93.34,79.38 IC8.8
N$17
  Top 0.254: IC2.36 62.23,63.5 62.87,64.14 64.77,64.14 66.04,65.41 84.45,65.41 85.72,64.14 IC5.13
N$18
  Top 0.254: 86.36,80.64 86.36,83.19 JP6.1 | 86.36,80.64 86.36,80.01 IC8.11 | 86.36,80.64 104.78,80.64 104.78,75.56 102.87,73.66 JP1.1
N$19
  Top 0.254: IC2.26 62.23,38.1 65.41,38.1 C3.1
N$20
  Top 0.254: R5.1 75.56,20.32 74.3,20.32 D1.C 73.66,21.59 73.66,25.4 | 73.66,25.4 74.3,25.4 C1.2 | 73.66,25.4 71.75,25.4 C2.2
N$21
  Bottom 0.254: IC7.1 81.28,26.67 85.09,30.48 85.09,35.56 80.01,35.56 69.85,45.72 67.31,45.72 62.23,50.8 IC2.31
N$22
  Bottom 0.254: IC2.30 62.23,48.26 67.31,43.18 71.12,43.18 79.38,34.92 81.92,34.92 83.19,33.66 IC7.13
N$24  (via drill 0.61)
  Top 0.254: v62.87,39.37 59.69,39.37 59.05,38.73 47.62,38.73 46.99,38.1 IC2.15 | v81.92,28.57 83.19,27.3 84.45,27.3 85.72,26.04 IC7.3
  Bottom 0.254: v62.87,39.37 62.87,29.21 81.28,29.21 v81.92,28.57
N$25
  Bottom 0.254: IC8.3 84.45,71.75 88.9,76.2 100.33,76.2 JP1.2
N$26
  Top 0.254: IC8.2 81.92,70.48 83.19,69.22 89.53,69.22 90.81,70.48 IC8.6
PUMP
  Top 0.254: IC2.23 62.23,30.48 63.5,29.21 69.22,29.21 70.48,30.48 C2.1 71.75,30.48 74.3,30.48 C1.1
R/W\
  Bottom 0.254: 30.48,25.4 31.75,25.4 IC1.21 | 30.48,25.4 26.67,25.4 26.67,16.51 20.95,10.79 IC3.1 | 30.48,25.4 30.48,58.42 31.75,59.69 34.29,59.69 45.09,70.48 IC2.2
RE\
  Top 0.254: IC3.2 22.23,10.79 19.05,13.97 13.34,13.97 11.43,15.88 11.43,48.26 12.7,48.26 16.51,52.07 19.05,52.07 31.75,64.77 43.18,64.77 44.45,66.04 IC2.4
READDATA
  Top 0.254: JP4.30 116.2,53.34 109.86,53.34 R2.1
  Bottom 0.254: IC5.12 89.53,62.87 95.25,57.15 95.25,53.98 109.22,53.98 R2.1
RPW
  Top 0.254: IC2.18 44.45,30.48 43.18,30.48 42.55,30.48 40.64,32.38 R7.2
RST\  (via drill 0.61)
  Top 0.254: IC1.34 31.75,58.42 31.11,58.42 31.11,40.01 31.75,39.37 34.92,39.37 34.92,36.83 43.81,27.94 44.45,27.94 IC2.19 46.99,27.94 v53.98,27.94
  Bottom 0.254: v53.98,27.94 53.98,25.4 56.52,22.86 66.04,22.86 71.12,17.78 78.74,17.78 85.72,10.79 IC9.3
SIDSEL\  (via drill 0.61)
  Top 0.254: v93.98,36.83 95.89,38.73 97.79,38.73 100.33,41.27 100.33,43.18 v97.79,43.18
  Bottom 0.254: v93.98,36.83 96.52,34.29 IC7.8 | v97.79,43.18 99.06,44.45 106.05,44.45 116.84,55.24 JP4.32
STEP
  Top 0.254: IC7.4 89.53,26.04 90.81,27.3 94.61,27.3 97.79,30.48 100.33,30.48 106.68,36.83 107.95,35.56 107.95,34.29 117.47,34.29 118.11,34.92 118.11,40.01 116.84,40.01 JP4.20
TEST\
  Top 0.254: IC2.22 62.23,27.94 64.77,27.94 JP3.2
TRACK00
  Top 0.254: JP4.26 116.2,48.26 104.78,48.26 R4.1
  Bottom 0.254: IC5.2 81.92,55.24 87,50.16 101.6,50.16 103.5,48.26 R4.1
VCC  (via drill 0.61)
  Top 0.508: R6.2 70.48,53.34 | R6.2 71.75,53.34 73.03,53.34 74.3,53.34 76.2,53.34 80.64,48.9 IC4.14 81.92,47.62 83.82,45.72 97.16,45.72 98.42,46.99 BYP4.1 | BYP1.1 28.57,78.74 50.16,78.74 BYP2.1 51.44,78.74 52.7,77.47 78.74,77.47 | 85.72,73.03 81.28,77.47 IC8.13 80.64,78.11 79.38,78.11 IC8.14 | 85.72,73.03 86.36,72.39 IC8.4 | 85.72,73.03 88.9,73.03 | 88.9,73.03 91.44,73.03 95.89,77.47 BYP8.1 96.52,76.83 99.06,76.83 99.06,62.87 BYP5.1 | 88.9,73.03 88.9,77.47 IC8.10 | 78.74,77.47 78.74,72.39 IC8.1 | 78.74,77.47 IC8.14 | 78.74,77.47 IC8.14 | IC1.20 19.05,25.4 20.32,26.67 36.83,26.67 37.47,26.67 38.1,26.04 R7.1 | R10.2 12.7,29.84 16.51,26.04 17.14,26.04 IC1.20 | 44.45,16.51 45.72,16.51 IC6.20 | 44.45,16.51 38.73,16.51 BYP3.1 38.1,17.14 38.1,20.32 v37.47,20.95 23.5,20.95 20.95,18.41 IC3.14 19.68,18.41 17.78,20.32 v14.61,20.32 | IC2.21 62.23,25.4 64.77,25.4 JP3.3 67.31,25.4 68.58,24.13 71.12,24.13 71.12,17.14 BYP6.1 70.48,16.51 67.94,13.97 44.45,13.97 44.45,16.51 | 99.06,34.92 99.06,36.2 R11.2 | 99.06,34.92 99.06,32.38 BYP7.1 | 92.71,15.88 83.19,15.88 81.92,17.14 IC9.16 81.28,19.05 80.01,19.05 80.01,28.57 81.28,29.84 | 92.71,15.88 101.6,15.88 BYP9.1 | 81.28,29.84 81.28,31.75 IC7.14 | 99.06,34.92 93.34,34.92 92.71,34.29 92.71,30.48 83.82,30.48 83.19,29.84 81.28,29.84 | 70.48,53.34 67.94,50.8 66.67,50.8 R8.1 | R6.2 70.48,53.34 | v20.32,23.5 19.68,23.5 18.41,24.77 IC1.20 | R4.2 104.78,58.42 106.68,60.33 R1.2 | v105.41,81.28 105.41,71.12 | 105.41,71.12 105.41,64.14 109.22,64.14 | 109.22,64.14 R2.2 | 109.22,64.14 R2.2 | 105.41,71.12 115.57,71.12 JP8.1 | 109.22,64.14 109.22,65.41 C5.+ | 109.22,64.14 R2.2
  Top 0.508: 92.71,15.88 92.71,19.68 93.98,20.95 R9.2
  Bottom 0.508: IC8.1 78.74,69.85 78.74,64.77 IC5.16 78.74,62.23 73.66,62.23 73.66,53.98 71.12,53.98 R6.2 | JP3.3 66.67,24.77 73.03,18.41 80.64,18.41 IC9.16 | v37.47,20.95 38.1,20.95 | BYP1.1 27.94,78.11 27.94,33.66 27.3,33.66 19.05,25.4 IC1.20 | v20.32,23.5 20.32,19.05 IC3.14 | R3.2 108.58,35.56 107.31,36.83 99.69,36.83 R11.2 | R2.2 109.22,62.87 107.31,60.96 R1.2 | v14.61,20.32 14.61,81.28 v105.41,81.28
W_PROT
  Top 0.254: JP4.28 116.2,50.8 107.31,50.8 R1.1
  Bottom 0.254: IC5.14 84.45,62.87 90.17,57.15 90.17,51.44 106.68,51.44 R1.1
WPW
  Top 0.254: IC2.33 62.23,55.88 66.04,55.88 66.67,55.88 68.58,57.78 R8.2
WRITEDATA  (via drill 0.61)
  Top 0.254: v101.6,19.05 97.79,22.86 86.36,22.86 84.45,24.77 IC7.2
  Bottom 0.254: v101.6,19.05 104.78,15.88 110.49,15.88 115.57,20.95 115.57,24.13 120.02,24.13 121.28,25.4 121.28,46.99 116.2,46.99 115.57,46.35 115.57,43.81 116.84,43.81 JP4.22
WRITEGATE  (via drill 0.61)
  Top 0.254: v86.36,29.21 v91.44,29.21 | v102.23,25.4 v104.78,25.4
  Bottom 0.254: v86.36,29.21 86.36,31.75 IC7.12 | v91.44,29.21 92.71,27.94 99.69,27.94 v102.23,25.4 | v104.78,25.4 106.05,26.67 120.02,26.67 120.65,27.3 120.65,44.45 118.75,44.45 117.47,45.72 JP4.24

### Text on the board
Top: Component Side
Bottom: PA8PDP/VRS | Solder side
tPlace: - | - | + | + | - | + | RealConsole Floppy - Rev.1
